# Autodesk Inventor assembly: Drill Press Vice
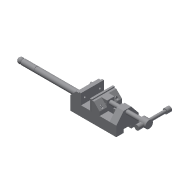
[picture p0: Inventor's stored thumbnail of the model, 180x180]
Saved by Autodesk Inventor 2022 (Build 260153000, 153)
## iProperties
Created: 2009-05
Part Number: Drill Press Vice
Document SubType Name: Assembly
Designer: Sham
Author: Sham
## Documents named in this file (9)
- D:\PROJECTS_2021\Resources\Tutorial Files\c12_Inv_2021_tut\c12_Inv_tut_2021\c12_tut03_inv\Drill Press Vice.iam
- D:\PROJECTS_2021\Resources\Tutorial Files\c12_Inv_2021_tut\c12_Inv_tut_2021\c12_tut03_inv\Base.ipt
- D:\PROJECTS_2021\Resources\Tutorial Files\c12_Inv_2021_tut\c12_Inv_tut_2021\c12_tut03_inv\Safety Handle.ipt
- D:\PROJECTS_2021\Resources\Tutorial Files\c12_Inv_2021_tut\c12_Inv_tut_2021\c12_tut03_inv\Jaw Face.ipt
- D:\PROJECTS_2021\Resources\Tutorial Files\c12_Inv_2021_tut\c12_Inv_tut_2021\c12_tut03_inv\Movable Jaw.ipt
- D:\PROJECTS_2021\Resources\Tutorial Files\c12_Inv_2021_tut\c12_Inv_tut_2021\c12_tut03_inv\Cap Screw.ipt
- D:\PROJECTS_2021\Resources\Tutorial Files\c12_Inv_2021_tut\c12_Inv_tut_2021\c12_tut03_inv\Clamp Screw Handle.ipt
- D:\PROJECTS_2021\Resources\Tutorial Files\c12_Inv_2021_tut\c12_Inv_tut_2021\c12_tut03_inv\Clamp Screw.ipt
- D:\PROJECTS_2021\Resources\Tutorial Files\c12_Inv_2021_tut\c12_Inv_tut_2021\c12_tut03_inv\Handle Stop.ipt
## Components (13 placed, 8 different names)
1. Base:1 — Mate:2, Mate:3, Mate:7, Insert:10, Insert:11, Insert:12, Insert:13
2. Safety Handle:1
3. Jaw Face:1 — Insert:8, Insert:9, Mate:7
4. Jaw Face:2 — Insert:10, Insert:11
5. Movable Jaw:1 — Mate:2, Mate:3, Insert:2, Insert:3, Insert:4, Insert:8, Insert:9
6. Cap Screw:1 — Insert:2
7. Cap Screw:2 — Insert:3
8. Cap Screw:3 — Insert:13
9. Cap Screw:4 — Insert:12
10. Clamp Screw:1 — Insert:4, Mate:6, Rotation/Translation:2
11. Clamp Screw Handle:1 — Mate:6, Insert:5, Insert:6, Rotation/Translation:2
12. Handle Stop:1 — Insert:6, Mate:8
13. Handle Stop:2 — Insert:5
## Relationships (17: Insert 11, Mate 5, RelateRotateTranslate 1)
- Mate:2: Base:1 ↔ Movable Jaw:1
- Mate:3: Base:1 ↔ Movable Jaw:1
- Insert:2: Movable Jaw:1 ↔ Cap Screw:1
- Insert:3: Movable Jaw:1 ↔ Cap Screw:2
- Insert:4: Movable Jaw:1 ↔ Clamp Screw:1
- Mate:6: Clamp Screw:1 ↔ Clamp Screw Handle:1
- Insert:5: Clamp Screw Handle:1 ↔ Handle Stop:2
- Insert:6: Clamp Screw Handle:1 ↔ Handle Stop:1
- Insert:8: Jaw Face:1 ↔ Movable Jaw:1
- Insert:9: Jaw Face:1 ↔ Movable Jaw:1
- Mate:7: Base:1 ↔ Jaw Face:1
- Rotation/Translation:2 [RelateRotateTranslate]: Clamp Screw:1 ↔ Clamp Screw Handle:1
- Mate:8: Handle Stop:1
- Insert:10: Base:1 ↔ Jaw Face:2
- Insert:11: Base:1 ↔ Jaw Face:2
- Insert:12: Base:1 ↔ Cap Screw:4
- Insert:13: Base:1 ↔ Cap Screw:3
